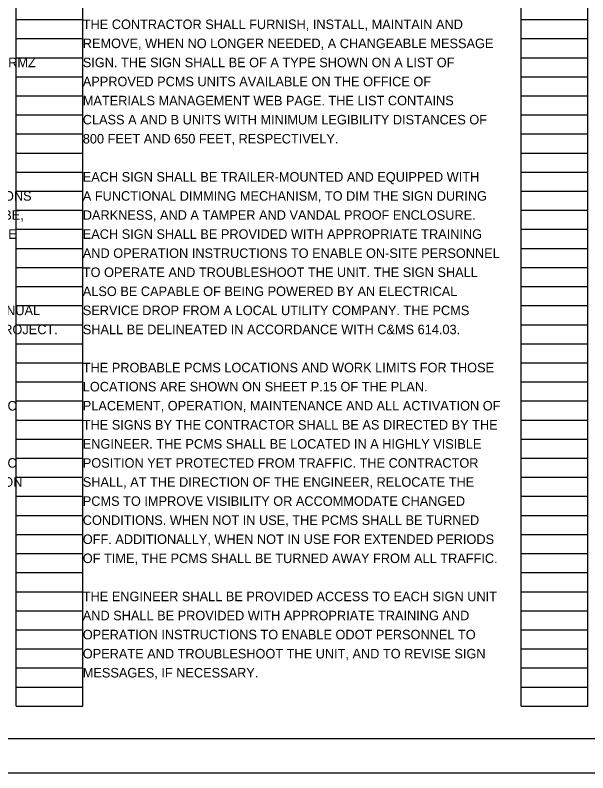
# Model space of a CAD drawing. Extents: x 0 to 34, y 0 to 22.
# Drawn here: x 16.25 to 24.66, y 0 to 11.12 of the extents above; entities that cross this region are included whole.
import ezdxf

# ---------------------------------------------------------------- set-up
doc = ezdxf.new("R2010")
doc.units = 0
for name, color, linetype in [('SH_Border', 7, 'Continuous'), ('SH_Cut_Line', 7, 'Continuous'), ('SH_Data', 7, 'Continuous'), ('SH_Text', 7, 'Continuous')]:
    doc.layers.add(name, color=color, linetype=linetype)

msp = doc.modelspace()

# ---------------------------------------------------------------- linework, layer by layer
at = {"layer": 'SH_Border'}
msp.add_lwpolyline([(1.5, 21.5), (33.5, 21.5), (33.5, 0.5), (1.5, 0.5)], close=True, dxfattribs=at)
at = {"layer": 'SH_Cut_Line'}
msp.add_lwpolyline([(0, 0), (34, 0), (34, 22), (0, 22)], close=True, dxfattribs=at)
at = {"layer": 'SH_Data'}
for p, q in [((16.26, 0.98), (16.26, 21.14)), ((17.24, 0.98), (17.24, 21.14)), ((23.68, 0.98), (23.68, 21.14)), ((24.66, 0.98), (24.66, 21.14)), ((16.26, 11.06), (17.24, 11.06)), ((23.68, 11.06), (24.66, 11.06)), ((16.26, 10.78), (17.24, 10.78)), ((23.68, 10.78), (24.66, 10.78)), ((16.26, 10.5), (17.24, 10.5)), ((23.68, 10.5), (24.66, 10.5)), ((16.26, 10.22), (17.24, 10.22)), ((23.68, 10.22), (24.66, 10.22)), ((16.26, 9.94), (17.24, 9.94)), ((23.68, 9.94), (24.66, 9.94)), ((16.26, 9.66), (17.24, 9.66)), ((23.68, 9.66), (24.66, 9.66)), ((16.26, 9.38), (17.24, 9.38)), ((23.68, 9.38), (24.66, 9.38)), ((16.26, 9.1), (17.24, 9.1)), ((23.68, 9.1), (24.66, 9.1)), ((16.26, 8.82), (17.24, 8.82)), ((23.68, 8.82), (24.66, 8.82)), ((16.26, 8.54), (17.24, 8.54)), ((23.68, 8.54), (24.66, 8.54)), ((16.26, 8.26), (17.24, 8.26)), ((23.68, 8.26), (24.66, 8.26)), ((16.26, 7.98), (17.24, 7.98)), ((23.68, 7.98), (24.66, 7.98)), ((16.26, 7.7), (17.24, 7.7)), ((23.68, 7.7), (24.66, 7.7)), ((16.26, 7.42), (17.24, 7.42)), ((23.68, 7.42), (24.66, 7.42)), ((16.26, 7.14), (17.24, 7.14)), ((23.68, 7.14), (24.66, 7.14)), ((16.26, 6.86), (17.24, 6.86)), ((23.68, 6.86), (24.66, 6.86)), ((16.26, 6.58), (17.24, 6.58)), ((23.68, 6.58), (24.66, 6.58)), ((16.26, 6.3), (17.24, 6.3)), ((23.68, 6.3), (24.66, 6.3)), ((16.26, 6.02), (17.24, 6.02)), ((23.68, 6.02), (24.66, 6.02)), ((16.26, 5.74), (17.24, 5.74)), ((23.68, 5.74), (24.66, 5.74)), ((16.26, 5.46), (17.24, 5.46)), ((23.68, 5.46), (24.66, 5.46)), ((16.26, 5.18), (17.24, 5.18)), ((23.68, 5.18), (24.66, 5.18)), ((16.26, 4.9), (17.24, 4.9)), ((23.68, 4.9), (24.66, 4.9)), ((16.26, 4.62), (17.24, 4.62)), ((23.68, 4.62), (24.66, 4.62)), ((16.26, 4.34), (17.24, 4.34)), ((23.68, 4.34), (24.66, 4.34)), ((16.26, 4.06), (17.24, 4.06)), ((23.68, 4.06), (24.66, 4.06)), ((16.26, 3.78), (17.24, 3.78)), ((23.68, 3.78), (24.66, 3.78)), ((16.26, 3.5), (17.24, 3.5)), ((23.68, 3.5), (24.66, 3.5)), ((16.26, 3.22), (17.24, 3.22)), ((23.68, 3.22), (24.66, 3.22)), ((16.26, 2.94), (17.24, 2.94)), ((23.68, 2.94), (24.66, 2.94)), ((16.26, 2.66), (17.24, 2.66)), ((23.68, 2.66), (24.66, 2.66)), ((16.26, 2.38), (17.24, 2.38)), ((23.68, 2.38), (24.66, 2.38)), ((16.26, 2.1), (17.24, 2.1)), ((23.68, 2.1), (24.66, 2.1)), ((16.26, 1.82), (17.24, 1.82)), ((23.68, 1.82), (24.66, 1.82)), ((16.26, 1.54), (17.24, 1.54)), ((23.68, 1.54), (24.66, 1.54)), ((16.26, 1.26), (17.24, 1.26)), ((23.68, 1.26), (24.66, 1.26)), ((16.26, 0.98), (17.24, 0.98)), ((23.68, 0.98), (24.66, 0.98))]:
    msp.add_line(p, q, dxfattribs=at)

# ---------------------------------------------------------------- texts
at = {"layer": 'SH_Text'}
for s, p in [('THE CONTRACTOR SHALL FURNISH, INSTALL, MAINTAIN AND', (17.24, 10.92)), ('REMOVE, WHEN NO LONGER NEEDED, A CHANGEABLE MESSAGE', (17.24, 10.64)), ('12. COMPLETE THE DEPARTMENT APPROVED (CA-D-8) WITHIN GOFORMZ', (9.82, 10.36)), ('SIGN. THE SIGN SHALL BE OF A TYPE SHOWN ON A LIST OF', (17.24, 10.36)), ('APPROVED PCMS UNITS AVAILABLE ON THE OFFICE OF', (17.24, 10.08)), ('MATERIALS MANAGEMENT WEB PAGE. THE LIST CONTAINS', (17.24, 9.8)), ('CLASS A AND B UNITS WITH MINIMUM LEGIBILITY DISTANCES OF', (17.24, 9.52)), ('800 FEET AND 650 FEET, RESPECTIVELY.', (17.24, 9.24)), ('EACH SIGN SHALL BE TRAILER-MOUNTED AND EQUIPPED WITH', (17.24, 8.68)), ('    ALONG WITH RECOMMENDED OR COMPLETED CORRECTIVE ACTIONS', (9.82, 8.4)), ('A FUNCTIONAL DIMMING MECHANISM, TO DIM THE SIGN DURING', (17.24, 8.4)), ('    AND THE DATES BY WHICH SUCH CORRECTIONS WERE, OR WILL BE,', (9.82, 8.12)), ('DARKNESS, AND A TAMPER AND VANDAL PROOF ENCLOSURE.', (17.24, 8.12)), ('    COMPLETED. A COPY OF THE CURRENT CA-D-8 DOCUMENT CAN BE', (9.82, 7.84)), ('EACH SIGN SHALL BE PROVIDED WITH APPROPRIATE TRAINING', (17.24, 7.84)), ('AND OPERATION INSTRUCTIONS TO ENABLE ON-SITE PERSONNEL', (17.24, 7.56)), ('TO OPERATE AND TROUBLESHOOT THE UNIT. THE SIGN SHALL', (17.24, 7.28)), ('ALSO BE CAPABLE OF BEING POWERED BY AN ELECTRICAL', (17.24, 7)), ('13. HAVE COPIES OF THE ODOT TEMPORARY TRAFFIC CONTROL MANUAL', (9.82, 6.72)), ('SERVICE DROP FROM A LOCAL UTILITY COMPANY. THE PCMS', (17.24, 6.72)), ('    AND CONTRACT DOCUMENTS AVAILABLE AT ALL TIMES ON THE PROJECT.', (9.82, 6.44)), ('SHALL BE DELINEATED IN ACCORDANCE WITH C&MS 614.03.', (17.24, 6.44)), ('THE PROBABLE PCMS LOCATIONS AND WORK LIMITS FOR THOSE', (17.24, 5.88)), ('LOCATIONS ARE SHOWN ON SHEET P.15 OF THE PLAN.', (17.24, 5.6)), ('A. THE PRORATED DAILY AMOUNT OF ITEM 614 MAINTAINING TRAFFIC', (9.82, 5.32)), ('PLACEMENT, OPERATION, MAINTENANCE AND ALL ACTIVATION OF', (17.24, 5.32)), ('THE SIGNS BY THE CONTRACTOR SHALL BE AS DIRECTED BY THE', (17.24, 5.04)), ('ENGINEER. THE PCMS SHALL BE LOCATED IN A HIGHLY VISIBLE', (17.24, 4.76)), ('   TO THE ORIGINAL BID AMOUNT FOR ITEM 614 MAINTAINING TRAFFIC', (9.82, 4.48)), ('POSITION YET PROTECTED FROM TRAFFIC. THE CONTRACTOR', (17.24, 4.48)), ('   DIVIDED BY THE DIFFERENCE BETWEEN THE ORIGINAL COMPLETION', (9.82, 4.2)), ('SHALL, AT THE DIRECTION OF THE ENGINEER, RELOCATE THE', (17.24, 4.2)), ('PCMS TO IMPROVE VISIBILITY OR ACCOMMODATE CHANGED', (17.24, 3.92)), ('CONDITIONS. WHEN NOT IN USE, THE PCMS SHALL BE TURNED', (17.24, 3.64)), ('OFF. ADDITIONALLY, WHEN NOT IN USE FOR EXTENDED PERIODS', (17.24, 3.36)), ('OF TIME, THE PCMS SHALL BE TURNED AWAY FROM ALL TRAFFIC.', (17.24, 3.08)), ('THE ENGINEER SHALL BE PROVIDED ACCESS TO EACH SIGN UNIT', (17.24, 2.52)), ('AND SHALL BE PROVIDED WITH APPROPRIATE TRAINING AND', (17.24, 2.24)), ('OPERATION INSTRUCTIONS TO ENABLE ODOT PERSONNEL TO', (17.24, 1.96)), ('OPERATE AND TROUBLESHOOT THE UNIT, AND TO REVISE SIGN', (17.24, 1.68)), ('MESSAGES, IF NECESSARY.', (17.24, 1.4))]:
    msp.add_text(s, height=0.14, dxfattribs=at).set_placement(p)

doc.saveas('drawing.dxf')
